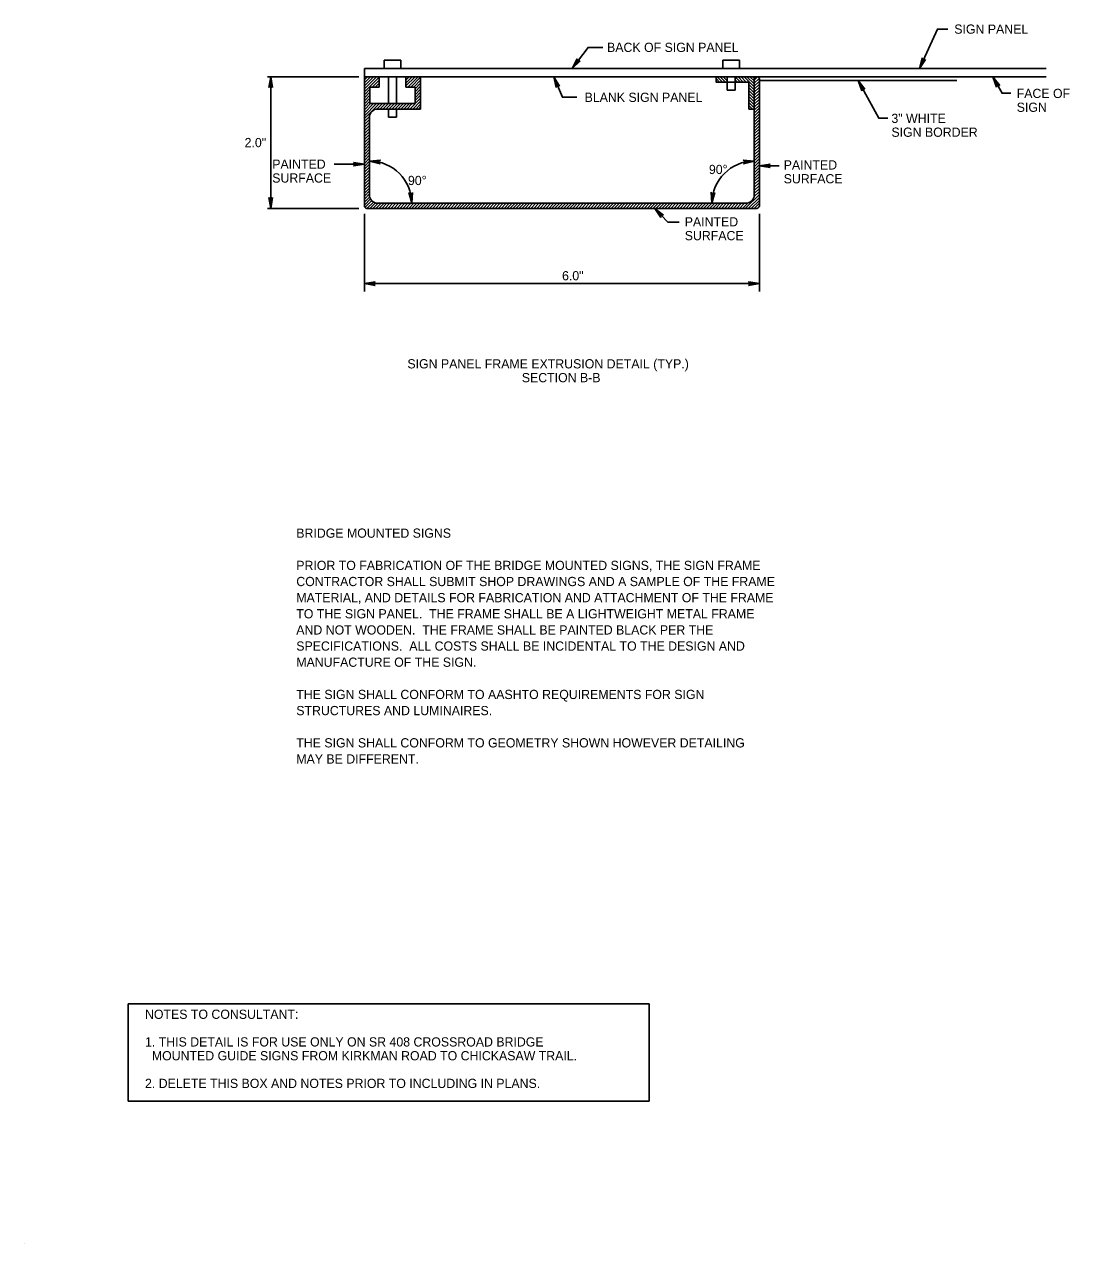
# Model space of a CAD drawing. Extents: x -897 to -114, y -697 to -235.
# Drawn here: x -897 to -500, y -697.4 to -234.5 of the extents above; entities that cross this region are included whole.
import ezdxf

# ---------------------------------------------------------------- set-up
doc = ezdxf.new("R2010")
doc.units = 0
for name, color, linetype in [('AdhocPoint_dp', 7, 'Continuous'), ('DimLines_dp', 7, 'Continuous'), ('SignMisc', 7, 'Continuous'), ('TextAlert', 7, 'Continuous'), ('TextLabel', 7, 'Continuous'), ('TextNotes', 7, 'Continuous')]:
    doc.layers.add(name, color=color, linetype=linetype)

msp = doc.modelspace()

# ---------------------------------------------------------------- linework, layer by layer
at = {"layer": 'AdhocPoint_dp'}
msp.add_line((-896.97, -697.44), (-896.97, -697.44), dxfattribs=at)
at = {"layer": 'DimLines_dp'}
for p, q in [((-769.94, -254.4), (-804.7, -254.4)), ((-804.08, -258.51), (-803.39, -254.4)), ((-803.74, -257.94), (-803.39, -254.4)), ((-803.39, -304.4), (-803.39, -254.4)), ((-803.39, -254.4), (-802.7, -258.52)), ((-803.05, -257.94), (-803.39, -254.4)), ((-803.39, -257.37), (-804.08, -258.51)), ((-802.7, -258.52), (-803.39, -257.37)), ((-765.91, -286.41), (-761.74, -286.09)), ((-762.36, -286.38), (-765.91, -286.41)), ((-761.88, -287.46), (-765.91, -286.41)), ((-762.42, -287.07), (-765.91, -286.41)), ((-761.74, -286.09), (-762.96, -286.67)), ((-762.96, -286.67), (-761.88, -287.46)), ((-623.97, -286.12), (-619.81, -286.41)), ((-622.77, -286.7), (-623.97, -286.12)), ((-619.81, -286.41), (-623.85, -287.49)), ((-623.85, -287.49), (-622.77, -286.7)), ((-623.37, -286.41), (-619.81, -286.41)), ((-623.3, -287.09), (-619.81, -286.41)), ((-803.39, -304.4), (-804.08, -300.27)), ((-804.08, -300.27), (-803.39, -301.43)), ((-803.74, -300.86), (-803.39, -304.4)), ((-802.7, -300.29), (-803.39, -304.4)), ((-803.39, -301.43), (-802.7, -300.29)), ((-803.05, -300.86), (-803.39, -304.4)), ((-749.88, -302.45), (-750.93, -298.4)), ((-750.93, -298.4), (-750.14, -299.49)), ((-750.53, -298.95), (-749.88, -302.45)), ((-750.14, -299.49), (-749.55, -298.29)), ((-749.55, -298.29), (-749.88, -302.45)), ((-749.84, -298.89), (-749.88, -302.45)), ((-635.85, -302.45), (-636.18, -298.28)), ((-636.18, -298.28), (-635.59, -299.49)), ((-635.89, -298.89), (-635.85, -302.45)), ((-634.8, -298.41), (-635.85, -302.45)), ((-635.2, -298.95), (-635.85, -302.45)), ((-635.59, -299.49), (-634.8, -298.41)), ((-769.94, -304.4), (-804.7, -304.4)), ((-767.86, -306.47), (-767.86, -335.93)), ((-617.86, -306.47), (-617.86, -335.93)), ((-767.86, -332.94), (-763.74, -332.25)), ((-764.32, -332.59), (-767.86, -332.94)), ((-617.86, -332.94), (-767.86, -332.94)), ((-763.75, -333.63), (-767.86, -332.94)), ((-764.32, -333.28), (-767.86, -332.94)), ((-763.74, -332.25), (-764.89, -332.94)), ((-764.89, -332.94), (-763.75, -333.63)), ((-617.86, -332.94), (-621.99, -333.63)), ((-621.99, -333.63), (-620.83, -332.94)), ((-621.97, -332.25), (-617.86, -332.94)), ((-620.83, -332.94), (-621.97, -332.25)), ((-621.4, -332.59), (-617.86, -332.94)), ((-621.4, -333.28), (-617.86, -332.94))]:
    msp.add_line(p, q, dxfattribs=at)
for centre, start, end in [((-765.91, -302.45), 0, 90), ((-619.81, -302.45), 90, 180)]:
    msp.add_arc(centre, 16.04, start, end, dxfattribs=at)
at = {"layer": 'SignMisc'}
for p, q in [((-754.05, -248.15), (-760.3, -248.15)), ((-760.3, -248.15), (-760.3, -251.27)), ((-754.05, -248.15), (-754.05, -251.27)), ((-631.68, -248.15), (-625.43, -248.15)), ((-631.68, -248.15), (-631.68, -251.27)), ((-625.43, -248.15), (-625.43, -251.27)), ((-767.86, -251.27), (-767.86, -303.4)), ((-508.92, -251.27), (-767.86, -251.27)), ((-508.92, -254.4), (-767.86, -254.4)), ((-767.86, -254.47), (-767.79, -254.4)), ((-767.86, -255.61), (-766.65, -254.4)), ((-767.86, -256.74), (-765.52, -254.4)), ((-767.86, -257.87), (-764.39, -254.4)), ((-767.86, -259), (-763.26, -254.4)), ((-767.86, -260.13), (-762.29, -254.56)), ((-762.29, -254.4), (-762.29, -258.3)), ((-758.74, -254.4), (-758.74, -264.55)), ((-755.61, -254.4), (-755.61, -264.55)), ((-752.06, -254.4), (-752.06, -258.3)), ((-752.06, -254.51), (-751.95, -254.4)), ((-752.06, -255.64), (-750.81, -254.4)), ((-752.06, -256.78), (-749.68, -254.4)), ((-752.06, -257.91), (-748.55, -254.4)), ((-751.32, -258.3), (-747.42, -254.4)), ((-750.19, -258.3), (-746.49, -254.59)), ((-746.49, -266.65), (-746.49, -254.4)), ((-634.31, -256.4), (-634.31, -254.4)), ((-631.87, -256.4), (-633.87, -254.4)), ((-630.74, -256.4), (-632.74, -254.4)), ((-630.11, -255.89), (-631.6, -254.4)), ((-630.11, -254.75), (-630.47, -254.4)), ((-630.11, -254.4), (-630.11, -259.52)), ((-626.99, -254.4), (-626.99, -259.52)), ((-625.08, -256.4), (-626.99, -254.48)), ((-623.95, -256.4), (-625.95, -254.4)), ((-622.82, -256.4), (-624.82, -254.4)), ((-619.81, -258.27), (-623.68, -254.4)), ((-619.81, -257.13), (-622.55, -254.4)), ((-619.81, -256), (-621.42, -254.4)), ((-619.81, -254.87), (-620.29, -254.4)), ((-619.81, -299.32), (-619.81, -254.4)), ((-619.81, -255.76), (-618.5, -254.45)), ((-767.86, -261.26), (-765.76, -259.16)), ((-765.76, -258.3), (-765.76, -264.55)), ((-762.29, -258.3), (-765.76, -258.3)), ((-764.9, -258.3), (-762.29, -255.69)), ((-763.77, -258.3), (-762.29, -256.82)), ((-762.63, -258.3), (-762.29, -257.95)), ((-748.59, -258.3), (-752.06, -258.3)), ((-749.06, -258.3), (-746.49, -255.73)), ((-748.59, -258.96), (-746.49, -256.86)), ((-748.59, -260.09), (-746.49, -257.99)), ((-748.59, -258.3), (-748.59, -264.55)), ((-748.59, -261.22), (-746.49, -259.12)), ((-633, -256.4), (-634.31, -255.08)), ((-634.13, -256.4), (-634.31, -256.21)), ((-621.81, -256.4), (-634.31, -256.4)), ((-626.21, -256.4), (-626.99, -255.62)), ((-621.81, -266.65), (-621.81, -256.4)), ((-619.81, -259.4), (-621.81, -257.4)), ((-619.81, -260.53), (-621.81, -258.53)), ((-619.81, -256.9), (-617.93, -255.01)), ((-619.81, -258.03), (-617.86, -256.08)), ((-619.81, -259.16), (-617.86, -257.21)), ((-619.81, -260.29), (-617.86, -258.34)), ((-617.86, -303.4), (-617.86, -255.37)), ((-542.86, -255.8), (-617.86, -255.8)), ((-767.86, -262.39), (-765.76, -260.29)), ((-767.86, -263.52), (-765.76, -261.42)), ((-767.86, -264.66), (-765.76, -262.56)), ((-767.86, -265.79), (-765.76, -263.69)), ((-750.62, -266.65), (-746.49, -262.51)), ((-749.49, -266.65), (-746.49, -263.65)), ((-748.59, -262.35), (-746.49, -260.25)), ((-748.59, -263.48), (-746.49, -261.38)), ((-630.11, -259.52), (-626.99, -259.52)), ((-619.81, -261.66), (-621.81, -259.66)), ((-619.81, -262.79), (-621.81, -260.79)), ((-619.81, -263.92), (-621.81, -261.92)), ((-619.81, -265.05), (-621.81, -263.05)), ((-619.81, -261.42), (-617.86, -259.47)), ((-619.81, -262.55), (-617.86, -260.6)), ((-619.81, -263.68), (-617.86, -261.73)), ((-619.81, -264.82), (-617.86, -262.87)), ((-767.86, -266.92), (-765.49, -264.55)), ((-767.86, -268.05), (-764.36, -264.55)), ((-767.86, -269.18), (-763.23, -264.55)), ((-767.86, -270.31), (-762.1, -264.55)), ((-748.59, -264.55), (-765.76, -264.55)), ((-763.09, -266.68), (-760.96, -264.55)), ((-746.49, -266.65), (-762.79, -266.65)), ((-761.93, -266.65), (-759.83, -264.55)), ((-760.8, -266.65), (-758.7, -264.55)), ((-759.67, -266.65), (-757.57, -264.55)), ((-758.74, -266.65), (-758.74, -269.77)), ((-758.54, -266.65), (-756.44, -264.55)), ((-757.41, -266.65), (-755.31, -264.55)), ((-756.28, -266.65), (-754.18, -264.55)), ((-755.61, -266.65), (-755.61, -269.77)), ((-755.15, -266.65), (-753.05, -264.55)), ((-754.01, -266.65), (-751.91, -264.55)), ((-752.88, -266.65), (-750.78, -264.55)), ((-751.75, -266.65), (-749.65, -264.55)), ((-748.36, -266.65), (-746.49, -264.78)), ((-747.23, -266.65), (-746.49, -265.91)), ((-619.81, -266.19), (-621.81, -264.19)), ((-620.49, -266.65), (-621.81, -265.32)), ((-621.62, -266.65), (-621.81, -266.45)), ((-621.81, -266.65), (-619.81, -266.65)), ((-619.81, -265.95), (-617.86, -264)), ((-619.81, -267.08), (-617.86, -265.13)), ((-619.81, -268.21), (-617.86, -266.26)), ((-619.81, -269.34), (-617.86, -267.39)), ((-767.86, -271.44), (-765.87, -269.45)), ((-767.86, -272.58), (-765.91, -270.63)), ((-767.86, -273.71), (-765.91, -271.76)), ((-767.86, -274.84), (-765.91, -272.89)), ((-765.91, -269.77), (-765.91, -299.32)), ((-755.61, -269.77), (-758.74, -269.77)), ((-619.81, -270.47), (-617.86, -268.52)), ((-619.81, -271.6), (-617.86, -269.65)), ((-619.81, -272.74), (-617.86, -270.79)), ((-619.81, -273.87), (-617.86, -271.92)), ((-619.81, -275), (-617.86, -273.05)), ((-767.86, -275.97), (-765.91, -274.02)), ((-767.86, -277.1), (-765.91, -275.15)), ((-767.86, -278.23), (-765.91, -276.28)), ((-767.86, -279.36), (-765.91, -277.41)), ((-619.81, -276.13), (-617.86, -274.18)), ((-619.81, -277.26), (-617.86, -275.31)), ((-619.81, -278.39), (-617.86, -276.44)), ((-619.81, -279.52), (-617.86, -277.57)), ((-767.86, -280.5), (-765.91, -278.55)), ((-767.86, -281.63), (-765.91, -279.68)), ((-767.86, -282.76), (-765.91, -280.81)), ((-767.86, -283.89), (-765.91, -281.94)), ((-619.81, -280.66), (-617.86, -278.71)), ((-619.81, -281.79), (-617.86, -279.84)), ((-619.81, -282.92), (-617.86, -280.97)), ((-619.81, -284.05), (-617.86, -282.1)), ((-767.86, -285.02), (-765.91, -283.07)), ((-767.86, -286.15), (-765.91, -284.2)), ((-767.86, -287.28), (-765.91, -285.33)), ((-767.86, -288.42), (-765.91, -286.47)), ((-619.81, -285.18), (-617.86, -283.23)), ((-619.81, -286.31), (-617.86, -284.36)), ((-619.81, -287.44), (-617.86, -285.49)), ((-619.81, -288.57), (-617.86, -286.62)), ((-767.86, -289.55), (-765.91, -287.6)), ((-767.86, -290.68), (-765.91, -288.73)), ((-767.86, -291.81), (-765.91, -289.86)), ((-767.86, -292.94), (-765.91, -290.99)), ((-619.81, -289.71), (-617.86, -287.76)), ((-619.81, -290.84), (-617.86, -288.89)), ((-619.81, -291.97), (-617.86, -290.02)), ((-619.81, -293.1), (-617.86, -291.15)), ((-767.86, -294.07), (-765.91, -292.12)), ((-767.86, -295.2), (-765.91, -293.25)), ((-767.86, -296.33), (-765.91, -294.38)), ((-767.86, -297.47), (-765.91, -295.52)), ((-619.81, -294.23), (-617.86, -292.28)), ((-619.81, -295.36), (-617.86, -293.41)), ((-619.81, -296.49), (-617.86, -294.54)), ((-619.81, -297.63), (-617.86, -295.68)), ((-767.86, -298.6), (-765.91, -296.65)), ((-767.86, -299.73), (-765.91, -297.78)), ((-767.86, -300.86), (-765.91, -298.91)), ((-767.86, -301.99), (-765.82, -299.95)), ((-767.86, -303.12), (-765.53, -300.79)), ((-623.19, -304.4), (-617.86, -299.07)), ((-622.06, -304.4), (-617.86, -300.2)), ((-619.9, -299.97), (-617.86, -297.94)), ((-619.81, -298.76), (-617.86, -296.81)), ((-767.64, -304.03), (-765.06, -301.45)), ((-766.87, -304.4), (-764.44, -301.96)), ((-766.86, -304.4), (-618.86, -304.4)), ((-765.74, -304.4), (-763.66, -302.31)), ((-764.61, -304.4), (-762.66, -302.45)), ((-763.48, -304.4), (-761.53, -302.45)), ((-762.79, -302.45), (-622.94, -302.45)), ((-762.35, -304.4), (-760.4, -302.45)), ((-761.22, -304.4), (-759.27, -302.45)), ((-760.09, -304.4), (-758.14, -302.45)), ((-758.95, -304.4), (-757, -302.45)), ((-757.82, -304.4), (-755.87, -302.45)), ((-756.69, -304.4), (-754.74, -302.45)), ((-755.56, -304.4), (-753.61, -302.45)), ((-754.43, -304.4), (-752.48, -302.45)), ((-753.3, -304.4), (-751.35, -302.45)), ((-752.17, -304.4), (-750.22, -302.45)), ((-751.03, -304.4), (-749.08, -302.45)), ((-749.9, -304.4), (-747.95, -302.45)), ((-748.77, -304.4), (-746.82, -302.45)), ((-747.64, -304.4), (-745.69, -302.45)), ((-746.51, -304.4), (-744.56, -302.45)), ((-745.38, -304.4), (-743.43, -302.45)), ((-744.25, -304.4), (-742.3, -302.45)), ((-743.11, -304.4), (-741.16, -302.45)), ((-741.98, -304.4), (-740.03, -302.45)), ((-740.85, -304.4), (-738.9, -302.45)), ((-739.72, -304.4), (-737.77, -302.45)), ((-738.59, -304.4), (-736.64, -302.45)), ((-737.46, -304.4), (-735.51, -302.45)), ((-736.33, -304.4), (-734.38, -302.45)), ((-735.2, -304.4), (-733.25, -302.45)), ((-734.06, -304.4), (-732.11, -302.45)), ((-732.93, -304.4), (-730.98, -302.45)), ((-731.8, -304.4), (-729.85, -302.45)), ((-730.67, -304.4), (-728.72, -302.45)), ((-729.54, -304.4), (-727.59, -302.45)), ((-728.41, -304.4), (-726.46, -302.45)), ((-727.28, -304.4), (-725.33, -302.45)), ((-726.14, -304.4), (-724.19, -302.45)), ((-725.01, -304.4), (-723.06, -302.45)), ((-723.88, -304.4), (-721.93, -302.45)), ((-722.75, -304.4), (-720.8, -302.45)), ((-721.62, -304.4), (-719.67, -302.45)), ((-720.49, -304.4), (-718.54, -302.45)), ((-719.36, -304.4), (-717.41, -302.45)), ((-718.22, -304.4), (-716.27, -302.45)), ((-717.09, -304.4), (-715.14, -302.45)), ((-715.96, -304.4), (-714.01, -302.45)), ((-714.83, -304.4), (-712.88, -302.45)), ((-713.7, -304.4), (-711.75, -302.45)), ((-712.57, -304.4), (-710.62, -302.45)), ((-711.44, -304.4), (-709.49, -302.45)), ((-710.31, -304.4), (-708.36, -302.45)), ((-709.17, -304.4), (-707.22, -302.45)), ((-708.04, -304.4), (-706.09, -302.45)), ((-706.91, -304.4), (-704.96, -302.45)), ((-705.78, -304.4), (-703.83, -302.45)), ((-704.65, -304.4), (-702.7, -302.45)), ((-703.52, -304.4), (-701.57, -302.45)), ((-702.39, -304.4), (-700.44, -302.45)), ((-701.25, -304.4), (-699.3, -302.45)), ((-700.12, -304.4), (-698.17, -302.45)), ((-698.99, -304.4), (-697.04, -302.45)), ((-697.86, -304.4), (-695.91, -302.45)), ((-696.73, -304.4), (-694.78, -302.45)), ((-695.6, -304.4), (-693.65, -302.45)), ((-694.47, -304.4), (-692.52, -302.45)), ((-693.33, -304.4), (-691.38, -302.45)), ((-692.2, -304.4), (-690.25, -302.45)), ((-691.07, -304.4), (-689.12, -302.45)), ((-689.94, -304.4), (-687.99, -302.45)), ((-688.81, -304.4), (-686.86, -302.45)), ((-687.68, -304.4), (-685.73, -302.45)), ((-686.55, -304.4), (-684.6, -302.45)), ((-685.41, -304.4), (-683.46, -302.45)), ((-684.28, -304.4), (-682.33, -302.45)), ((-683.15, -304.4), (-681.2, -302.45)), ((-682.02, -304.4), (-680.07, -302.45)), ((-680.89, -304.4), (-678.94, -302.45)), ((-679.76, -304.4), (-677.81, -302.45)), ((-678.63, -304.4), (-676.68, -302.45)), ((-677.5, -304.4), (-675.55, -302.45)), ((-676.36, -304.4), (-674.41, -302.45)), ((-675.23, -304.4), (-673.28, -302.45)), ((-674.1, -304.4), (-672.15, -302.45)), ((-672.97, -304.4), (-671.02, -302.45)), ((-671.84, -304.4), (-669.89, -302.45)), ((-670.71, -304.4), (-668.76, -302.45)), ((-669.58, -304.4), (-667.63, -302.45)), ((-668.44, -304.4), (-666.49, -302.45)), ((-667.31, -304.4), (-665.36, -302.45)), ((-666.18, -304.4), (-664.23, -302.45)), ((-665.05, -304.4), (-663.1, -302.45)), ((-663.92, -304.4), (-661.97, -302.45)), ((-662.79, -304.4), (-660.84, -302.45)), ((-661.66, -304.4), (-659.71, -302.45)), ((-660.52, -304.4), (-658.57, -302.45)), ((-659.39, -304.4), (-657.44, -302.45)), ((-658.26, -304.4), (-656.31, -302.45)), ((-657.13, -304.4), (-655.18, -302.45)), ((-656, -304.4), (-654.05, -302.45)), ((-654.87, -304.4), (-652.92, -302.45)), ((-653.74, -304.4), (-651.79, -302.45)), ((-652.61, -304.4), (-650.66, -302.45)), ((-651.47, -304.4), (-649.52, -302.45)), ((-650.34, -304.4), (-648.39, -302.45)), ((-649.21, -304.4), (-647.26, -302.45)), ((-648.08, -304.4), (-646.13, -302.45)), ((-646.95, -304.4), (-645, -302.45)), ((-645.82, -304.4), (-643.87, -302.45)), ((-644.69, -304.4), (-642.74, -302.45)), ((-643.55, -304.4), (-641.6, -302.45)), ((-642.42, -304.4), (-640.47, -302.45)), ((-641.29, -304.4), (-639.34, -302.45)), ((-640.16, -304.4), (-638.21, -302.45)), ((-639.03, -304.4), (-637.08, -302.45)), ((-637.9, -304.4), (-635.95, -302.45)), ((-636.77, -304.4), (-634.82, -302.45)), ((-635.63, -304.4), (-633.68, -302.45)), ((-634.5, -304.4), (-632.55, -302.45)), ((-633.37, -304.4), (-631.42, -302.45)), ((-632.24, -304.4), (-630.29, -302.45)), ((-631.11, -304.4), (-629.16, -302.45)), ((-629.98, -304.4), (-628.03, -302.45)), ((-628.85, -304.4), (-626.9, -302.45)), ((-627.71, -304.4), (-625.76, -302.45)), ((-626.58, -304.4), (-624.63, -302.45)), ((-625.45, -304.4), (-623.5, -302.45)), ((-624.32, -304.4), (-622.28, -302.35)), ((-620.93, -304.4), (-617.86, -301.33)), ((-619.8, -304.4), (-617.86, -302.46)), ((-618.64, -304.37), (-617.89, -303.62))]:
    msp.add_line(p, q, dxfattribs=at)
for centre, radius, start, end in [((-618.84, -255.37), 0.975, 0, 180), ((-762.79, -269.77), 3.12, 90, 180), ((-762.79, -299.32), 3.12, 180, 270), ((-622.94, -299.32), 3.12, 270, 0), ((-766.86, -303.4), 1, 180, 270), ((-618.86, -303.4), 1, 270, 0)]:
    msp.add_arc(centre, radius, start, end, dxfattribs=at)
at = {"layer": 'TextAlert'}
for p, q in [((-857.57, -606.35), (-659.76, -606.35)), ((-857.57, -606.35), (-857.57, -643.4)), ((-659.76, -606.35), (-659.76, -643.4)), ((-857.57, -643.4), (-659.76, -643.4))]:
    msp.add_line(p, q, dxfattribs=at)
at = {"layer": 'TextLabel'}
for p, q in [((-688.97, -251.27), (-687.02, -247.57)), ((-687.1, -248.24), (-688.97, -251.27)), ((-685.93, -248.42), (-688.97, -251.27)), ((-686.55, -248.66), (-688.97, -251.27)), ((-687.02, -247.57), (-687.17, -248.91)), ((-687.17, -248.91), (-685.93, -248.42)), ((-557.07, -251.27), (-555.98, -247.23)), ((-554.73, -247.82), (-557.07, -251.27)), ((-555.91, -247.91), (-557.07, -251.27)), ((-555.28, -248.2), (-557.07, -251.27)), ((-555.98, -247.23), (-555.83, -248.57)), ((-555.83, -248.57), (-554.73, -247.82)), ((-694.99, -258.45), (-695.96, -254.4)), ((-695.96, -254.4), (-693.72, -257.93)), ((-694.26, -257.52), (-695.96, -254.4)), ((-694.9, -257.79), (-695.96, -254.4)), ((-527.78, -258.33), (-529.15, -254.4)), ((-529.15, -254.4), (-526.56, -257.68)), ((-527.15, -257.33), (-529.15, -254.4)), ((-527.75, -257.66), (-529.15, -254.4)), ((-694.8, -257.13), (-694.99, -258.45)), ((-693.72, -257.93), (-694.8, -257.13)), ((-578.99, -259.74), (-580.36, -255.8)), ((-580.36, -255.8), (-577.77, -259.08)), ((-578.36, -258.74), (-580.36, -255.8)), ((-578.96, -259.07), (-580.36, -255.8)), ((-578.93, -258.4), (-578.99, -259.74)), ((-577.77, -259.08), (-578.93, -258.4)), ((-527.72, -257), (-527.78, -258.33)), ((-526.56, -257.68), (-527.72, -257)), ((-771.97, -286.9), (-767.86, -287.59)), ((-770.83, -287.59), (-771.97, -286.9)), ((-767.86, -287.59), (-779.31, -287.59)), ((-767.86, -287.59), (-771.99, -288.28)), ((-771.99, -288.28), (-770.83, -287.59)), ((-771.4, -287.25), (-767.86, -287.59)), ((-771.4, -287.94), (-767.86, -287.59)), ((-617.86, -288.22), (-613.74, -287.53)), ((-614.32, -287.88), (-617.86, -288.22)), ((-617.86, -288.22), (-610.39, -288.22)), ((-613.75, -288.91), (-617.86, -288.22)), ((-614.32, -288.57), (-617.86, -288.22)), ((-613.74, -287.53), (-614.89, -288.22)), ((-614.89, -288.22), (-613.75, -288.91)), ((-655.22, -307.86), (-657.53, -304.4)), ((-657.53, -304.4), (-654.2, -306.93)), ((-654.85, -306.74), (-657.53, -304.4)), ((-655.35, -307.21), (-657.53, -304.4)), ((-654.2, -306.93), (-655.49, -306.56)), ((-655.49, -306.56), (-655.22, -307.86))]:
    msp.add_line(p, q, dxfattribs=at)
for points in [[(-546.3, -236.28), (-550.21, -236.28), (-557.07, -251.27)], [(-677.36, -243.24), (-682.87, -243.24), (-688.97, -251.27)], [(-687.15, -262.21), (-692.65, -262.21), (-695.96, -254.4)], [(-522.33, -260.68), (-525.7, -260.68), (-529.15, -254.4)], [(-569.11, -270.15), (-572.48, -270.15), (-580.36, -255.8)], [(-648.31, -309.65), (-652.59, -309.65), (-657.53, -304.4)]]:
    msp.add_lwpolyline(points, dxfattribs=at)

# ---------------------------------------------------------------- texts
at = {"layer": 'DimLines_dp'}
for s, p in [('2.0"', (-813.33, -281.14)), ('90°', (-637.01, -291.35)), ('90°', (-751.3, -295.53)), ('6.0"', (-692.79, -331.69))]:
    msp.add_text(s, height=3.5, dxfattribs=at).set_placement(p)
at = {"layer": 'TextAlert'}
for s, p in [('NOTES TO CONSULTANT:', (-851.16, -612.1)), ('1. THIS DETAIL IS FOR USE ONLY ON SR 408 CROSSROAD BRIDGE', (-851.16, -622.6)), ('  MOUNTED GUIDE SIGNS FROM KIRKMAN ROAD TO CHICKASAW TRAIL.', (-851.16, -627.85)), ('2. DELETE THIS BOX AND NOTES PRIOR TO INCLUDING IN PLANS.', (-851.16, -638.35))]:
    msp.add_text(s, height=3.5, dxfattribs=at).set_placement(p)
at = {"layer": 'TextLabel'}
for s, p in [('SIGN PANEL', (-543.84, -238.07)), ('BACK OF SIGN PANEL', (-675.69, -244.99)), ('FACE OF', (-520.13, -262.48)), ('BLANK SIGN PANEL', (-684.22, -263.96)), ('3" WHITE', (-567.71, -271.95)), ('SIGN', (-520.13, -267.73)), ('SIGN BORDER', (-567.71, -277.2)), ('PAINTED', (-802.84, -289.34)), ('PAINTED', (-608.61, -289.63)), ('SURFACE', (-802.84, -294.59)), ('SURFACE', (-608.61, -294.88)), ('PAINTED', (-646.19, -311.22)), ('SURFACE', (-646.19, -316.47)), ('SIGN PANEL FRAME EXTRUSION DETAIL (TYP.)', (-751.52, -365.14)), ('SECTION B-B', (-708.07, -370.39))]:
    msp.add_text(s, height=3.5, dxfattribs=at).set_placement(p)
at = {"layer": 'TextNotes'}
for s, p in [('BRIDGE MOUNTED SIGNS', (-793.71, -429.43)), ('PRIOR TO FABRICATION OF THE BRIDGE MOUNTED SIGNS, THE SIGN FRAME', (-793.71, -441.68)), ('CONTRACTOR SHALL SUBMIT SHOP DRAWINGS AND A SAMPLE OF THE FRAME', (-793.71, -447.8)), ('MATERIAL, AND DETAILS FOR FABRICATION AND ATTACHMENT OF THE FRAME', (-793.71, -453.93)), ('TO THE SIGN PANEL.  THE FRAME SHALL BE A LIGHTWEIGHT METAL FRAME', (-793.71, -460.05)), ('AND NOT WOODEN.  THE FRAME SHALL BE PAINTED BLACK PER THE', (-793.71, -466.18)), ('SPECIFICATIONS.  ALL COSTS SHALL BE INCIDENTAL TO THE DESIGN AND', (-793.71, -472.3)), ('MANUFACTURE OF THE SIGN.', (-793.71, -478.43)), ('THE SIGN SHALL CONFORM TO AASHTO REQUIREMENTS FOR SIGN', (-793.71, -490.68)), ('STRUCTURES AND LUMINAIRES.', (-793.71, -496.8)), ('THE SIGN SHALL CONFORM TO GEOMETRY SHOWN HOWEVER DETAILING', (-793.71, -509.05)), ('MAY BE DIFFERENT.', (-793.71, -515.18))]:
    msp.add_text(s, height=3.5, dxfattribs=at).set_placement(p)

doc.saveas('drawing.dxf')
